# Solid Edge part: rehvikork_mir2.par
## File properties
Author: KULL
Template: Iso Metric Part.par
Last saved by: KULL
Revision: 2
Application: Solid Edge
Accuracy: 0,990
Username: KULL
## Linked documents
rehvikork.par
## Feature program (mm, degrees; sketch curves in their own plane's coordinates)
part copy "CopiedPart_1"
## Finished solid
Body 1: solid body, 93 faces, 217 edges, 128 vertices.
  Faces by surface: blend 40, spline 40, sphere 6, torus 3, cylinder 2, cone 1, plane 1
  Edges by curve: intersection 128, circle 49, line 40
Bounding box of the edges (mm; curved faces can reach further): 4.951 x 16.000 x 16.000, from (-4, -8, -8) to (0.951, 8, 8).
Cylindrical faces by radius (mm): R7 x1, R8 x1
Conical faces (half-angle, radius in mm at the cone's reference point): 11.8765 deg R7 x1
Toroidal faces (ring radius, tube radius in mm): R7.0618 r0.08 x1, R7.6 r0.4 x1, R7.92 r0.08 x1
Spherical faces by radius (mm): R33.0132 x1, R33.5132 x2, R34.0132 x3
Planar faces by outward normal: -x 1
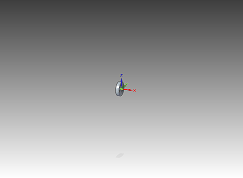
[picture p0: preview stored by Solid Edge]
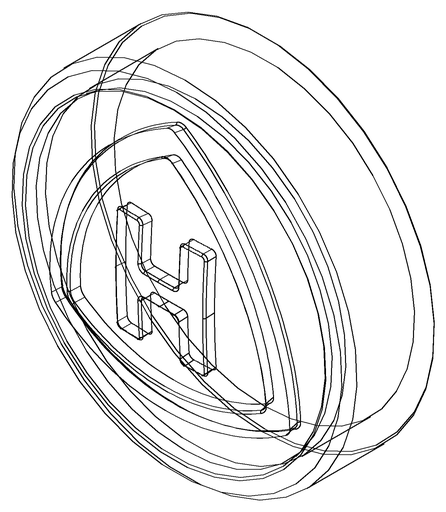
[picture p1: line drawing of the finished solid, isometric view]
